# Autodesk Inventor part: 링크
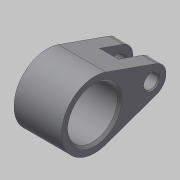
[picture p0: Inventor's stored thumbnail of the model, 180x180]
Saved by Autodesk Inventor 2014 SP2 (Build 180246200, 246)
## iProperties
Created: 2016-08
Part Number: 링크
Material: 강철, 탄소
Document SubType Name: Modeling
Designer: mduedu
Density: 7.87 g/cm^3
Appearance: 기본값
Author: mduedu
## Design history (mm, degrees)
sketch "스케치1"
  geometry: L1 (26, 5.657)-(4.667, 13.199); L2 (26, -5.657)-(4.667, -13.199); C1 r 10.5 at (0, 0); C2 r 3 at (24, 0); A1 r 14 centre (0, 0) between (4.667, 13.199) and (4.667, -13.199); A2 r 6 centre (24, 0) between (26, 5.657) and (26, -5.657); 1 further point
  constraints: 4 centre point, 4 end point, 4 point on circle, 4 tangent, 3 coincident, 1 horizontal alignment
  dimensions: "d0" = 28 diameter of A1; "d2" = 12 diameter of A2; "d3" = 24 distance of A2.centre point (0, 0); "d4" = 21 diameter of C1; "d5" = 6 diameter of C2
extrude "돌출1" new body sketch "스케치1" stored distance "d6" = 20; taper "d7" = 0 deg
sketch "스케치2"
  geometry: L1 (-10, 30)-(10, 30) reference; L2 (0, 0)-(0, 30); L3 (-4, 30)-(4, 30); L4 (4, 30)-(4, 16); L5 (4, 16)-(-4, 16); L6 (-4, 16)-(-4, 30)
  constraints: 10 end point, 2 midpoint, 2 parallel, 1 horizontal, 1 perpendicular, 1 point on line
  dimensions: "d8" = 8 distance between parallel lines of L4 L6; "d10" = 14 distance of L3.end L4.end
extrude "돌출2" cut sketch "스케치2" stored distance "d11" = 20; taper "d12" = 0 deg
chamfer "모따기1" distance "d13" = 1; stored, may be unused: second distance "d14" = 2, angle "d15" = 45 deg
chamfer "모따기2" distance "d16" = 0.5; stored, may be unused: second distance "d17" = 2, angle "d18" = 45 deg
node "솔리드1"
